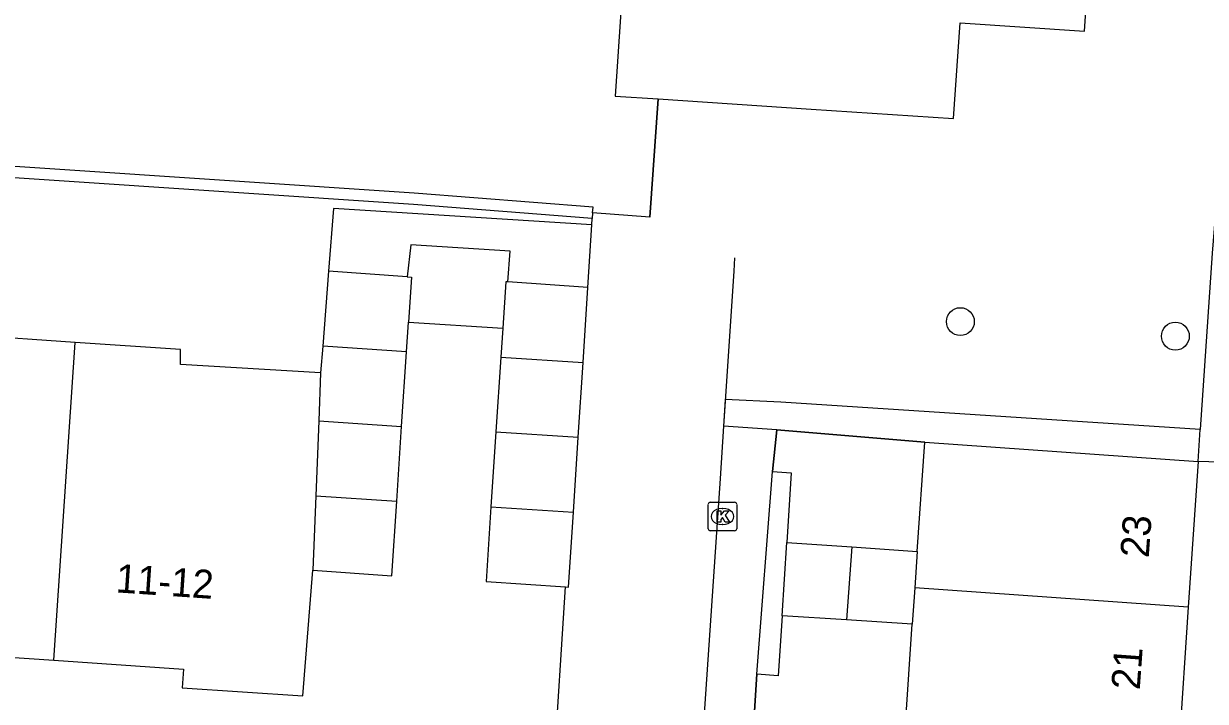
# Model space of a CAD drawing. Extents: x 161848 to 162726, y 385382 to 386521.
# Drawn here: x 162080.86 to 162122.26, y 386033.22 to 386056.94 of the extents above; entities that cross this region are included whole.
import ezdxf

# ---------------------------------------------------------------- set-up
doc = ezdxf.new("R2010")
doc.units = 0
for name, color, linetype in [('IMGEO_Boom', 7, 'Continuous'), ('IMGEO_Damwand', 7, 'Continuous'), ('IMGEO_Groenvoorziening', 7, 'Continuous'), ('IMGEO_Haag', 7, 'Continuous'), ('IMGEO_Hek', 7, 'Continuous'), ('IMGEO_Kolk', 7, 'Continuous'), ('IMGEO_Pand', 7, 'Continuous'), ('IMGEO_Pand_nummerreeks', 7, 'Continuous'), ('IMGEO_Voetpad_halfverhard', 7, 'Continuous'), ('IMGEO_Voetpad_open', 7, 'Continuous')]:
    doc.layers.add(name, color=color, linetype=linetype)

msp = doc.modelspace()

# ---------------------------------------------------------------- linework, layer by layer
at = {"layer": 'IMGEO_Boom'}
for centre in [(162113.677, 386046.507), (162121.21, 386045.999)]:
    msp.add_circle(centre, 0.489, dxfattribs=at)
at = {"layer": 'IMGEO_Damwand'}
for points in [[(162105.766, 386048.746), (162105.735, 386048.277), (162105.38, 386042.85), (162105.26, 386041.013)], [(162105.26, 386041.013), (162103.776, 386019.241), (162091.113, 386020.133), (162083.134, 386020.713), (162082.474, 386020.761)]]:
    msp.add_lwpolyline(points, dxfattribs=at)
at = {"layer": 'IMGEO_Groenvoorziening'}
for points in [[(162103.084, 386054.304), (162102.793, 386050.163), (162100.793, 386050.312)], [(162100.767, 386049.898), (162100.78, 386050.112)], [(162122.074, 386042.731), (162107.39, 386043.69), (162105.441, 386043.783), (162105.38, 386042.85)], [(162107.252, 386042.725), (162112.428, 386042.293)], [(162107.094, 386041.261), (162107.746, 386041.216), (162107.591, 386038.776)], [(162099.348, 386030.837), (162099.439, 386030.831), (162099.839, 386037.224)], [(162107.428, 386036.211), (162107.295, 386034.114), (162106.551, 386034.165)]]:
    msp.add_lwpolyline(points, dxfattribs=at)
at = {"layer": 'IMGEO_Haag'}
for points in [[(162100.793, 386050.312), (162100.809, 386050.511), (162094.545, 386051.001), (162049.411, 386054.017)], [(162100.78, 386050.112), (162094.517, 386050.603), (162049.384, 386053.618), (162049.397, 386053.818)], [(162100.793, 386050.312), (162100.78, 386050.112)]]:
    msp.add_lwpolyline(points, dxfattribs=at)
at = {"layer": 'IMGEO_Hek'}
for points in [[(162102.793, 386050.163), (162103.084, 386054.304)], [(162107.252, 386042.725), (162107.094, 386041.261)], [(162112.428, 386042.293), (162107.252, 386042.725)], [(162107.094, 386041.261), (162107.746, 386041.216), (162107.591, 386038.776)], [(162107.428, 386036.211), (162107.295, 386034.114), (162106.551, 386034.165)], [(162106.551, 386034.165), (162106.374, 386031.394)]]:
    msp.add_lwpolyline(points, dxfattribs=at)
at = {"layer": 'IMGEO_Kolk'}
for p, q in [((162104.84, 386039.26), (162104.84, 386040.112)), ((162104.915, 386040.186), (162105.767, 386040.186)), ((162105.328, 386039.966), (162105.353, 386039.966)), ((162105.841, 386040.112), (162105.841, 386039.26)), ((162105.767, 386039.186), (162104.915, 386039.186)), ((162105.351, 386039.406), (162105.326, 386039.406))]:
    msp.add_line(p, q, dxfattribs=at)
for points in [[(162104.84, 386039.26), (162104.84, 386040.112)], [(162104.915, 386040.186), (162105.767, 386040.186)], [(162105.161, 386039.886), (162105.284, 386039.886), (162105.284, 386039.735), (162105.414, 386039.886), (162105.578, 386039.886), (162105.432, 386039.735), (162105.585, 386039.486), (162105.433, 386039.486), (162105.348, 386039.65), (162105.284, 386039.583), (162105.284, 386039.486), (162105.161, 386039.486), (162105.161, 386039.886)], [(162105.841, 386040.112), (162105.841, 386039.26)], [(162105.767, 386039.186), (162104.915, 386039.186)]]:
    msp.add_lwpolyline(points, dxfattribs=at)
for centre, start, end in [((162104.917, 386040.11), 91.552, 178.448), ((162104.917, 386040.11), 91.552, 178.448), ((162105.765, 386040.11), 1.552, 88.448), ((162105.765, 386040.11), 1.552, 88.448), ((162104.917, 386039.262), 181.552, 268.448), ((162104.917, 386039.262), 181.552, 268.448), ((162105.765, 386039.262), 271.552, 358.448), ((162105.765, 386039.262), 271.552, 358.448)]:
    msp.add_arc(centre, 0.0765, start, end, dxfattribs=at)
for centre, major_axis, ratio, start_param, end_param in [((162105.327, 386039.686), (-0.387, 0.002), 0.722429, 4.712389, 7.853982), ((162105.352, 386039.686), (-0.39, 0.002), 0.717154, 1.570796, 4.712389)]:
    msp.add_ellipse(centre, major_axis=major_axis, ratio=ratio, start_param=start_param, end_param=end_param, dxfattribs=at)
at = {"layer": 'IMGEO_Pand'}
for points in [[(162103.084, 386054.304), (162108.452, 386053.946), (162113.44, 386053.614), (162113.664, 386056.962), (162118.028, 386056.671), (162118.642, 386065.873), (162114.274, 386066.165), (162114.973, 386076.64), (162109.771, 386076.987), (162110.19, 386083.26), (162108.794, 386083.353)], [(162091.103, 386077.734), (162090.775, 386072.799), (162090.435, 386067.702), (162102.421, 386066.903), (162101.588, 386054.404), (162103.084, 386054.304)], [(162100.767, 386049.898), (162091.712, 386050.469), (162091.541, 386048.276)], [(162100.625, 386047.703), (162100.767, 386049.898)], [(162097.825, 386047.896), (162097.901, 386048.97), (162094.42, 386049.194), (162094.289, 386048.078)], [(162091.541, 386048.276), (162091.336, 386045.647)], [(162094.289, 386048.078), (162091.541, 386048.276)], [(162094.289, 386048.078), (162094.445, 386048.067), (162094.341, 386046.487)], [(162097.825, 386047.896), (162097.756, 386047.901), (162097.648, 386046.283)], [(162100.625, 386047.703), (162097.825, 386047.896)], [(162100.456, 386045.082), (162100.625, 386047.703)], [(162094.273, 386045.454), (162094.341, 386046.487)], [(162094.341, 386046.487), (162097.648, 386046.283)], [(162097.648, 386046.283), (162097.58, 386045.267)], [(162082.667, 386045.779), (162078.977, 386046.029), (162078.95, 386045.517), (162074.049, 386045.837)], [(162081.914, 386034.653), (162082.667, 386045.779)], [(162091.263, 386044.717), (162086.349, 386045.003), (162086.358, 386045.529), (162082.667, 386045.779)], [(162091.336, 386045.647), (162091.263, 386044.717)], [(162094.273, 386045.454), (162091.336, 386045.647)], [(162094.101, 386042.841), (162094.273, 386045.454)], [(162097.58, 386045.267), (162097.406, 386042.646)], [(162097.58, 386045.267), (162100.456, 386045.082)], [(162100.287, 386042.46), (162100.456, 386045.082)], [(162091.263, 386044.717), (162091.195, 386043.032)], [(162091.195, 386043.032), (162091.089, 386040.414)], [(162091.195, 386043.032), (162094.101, 386042.841)], [(162093.93, 386040.228), (162094.101, 386042.841)], [(162097.406, 386042.646), (162097.231, 386040.025)], [(162097.406, 386042.646), (162100.287, 386042.46)], [(162100.117, 386039.839), (162100.287, 386042.46)], [(162112.165, 386038.462), (162112.428, 386042.293)], [(162112.428, 386042.293), (162122.011, 386041.611)], [(162122.011, 386041.611), (162121.664, 386036.509)], [(162091.089, 386040.414), (162090.984, 386037.804)], [(162091.089, 386040.414), (162093.93, 386040.228)], [(162090.984, 386037.804), (162093.758, 386037.615), (162093.93, 386040.228)], [(162097.231, 386040.025), (162097.057, 386037.41), (162099.839, 386037.224)], [(162097.231, 386040.025), (162100.117, 386039.839)], [(162099.839, 386037.224), (162099.948, 386037.217), (162100.117, 386039.839)], [(162107.428, 386036.211), (162107.591, 386038.776)], [(162107.591, 386038.776), (162109.878, 386038.619)], [(162109.878, 386038.619), (162109.691, 386036.067)], [(162109.878, 386038.619), (162112.165, 386038.462)], [(162112.165, 386038.462), (162112.078, 386037.191)], [(162081.914, 386034.653), (162086.459, 386034.346), (162086.415, 386033.692), (162090.642, 386033.414), (162090.984, 386037.804)], [(162112.078, 386037.191), (162111.991, 386035.921)], [(162121.664, 386036.509), (162112.078, 386037.191)], [(162121.664, 386036.509), (162121.339, 386031.726)], [(162109.691, 386036.067), (162107.428, 386036.211)], [(162111.991, 386035.921), (162109.691, 386036.067)], [(162111.75, 386032.408), (162111.991, 386035.921)], [(162073.288, 386034.59), (162077.368, 386034.304), (162077.41, 386034.958), (162081.914, 386034.653)]]:
    msp.add_lwpolyline(points, dxfattribs=at)
at = {"layer": 'IMGEO_Voetpad_halfverhard'}
for points in [[(162105.38, 386042.85), (162105.26, 386041.013), (162103.776, 386019.241), (162091.113, 386020.133), (162083.134, 386020.713)], [(162107.252, 386042.725), (162105.38, 386042.85)], [(162107.094, 386041.261), (162107.252, 386042.725)], [(162106.551, 386034.165), (162107.094, 386041.261)], [(162106.374, 386031.394), (162106.551, 386034.165)]]:
    msp.add_lwpolyline(points, dxfattribs=at)
at = {"layer": 'IMGEO_Voetpad_open'}
for points in [[(162125.487, 386090.674), (162122.884, 386053.657), (162122.5, 386048.906), (162122.074, 386042.731)], [(162122.011, 386041.611), (162122.074, 386042.731)], [(162123.495, 386041.562), (162122.011, 386041.611)]]:
    msp.add_lwpolyline(points, dxfattribs=at)

# ---------------------------------------------------------------- texts
at = {"layer": 'IMGEO_Pand_nummerreeks'}
for s, rotation, p in [('23', 85.9093, (162120.274, 386038.219)), ('23', 85.9093, (162120.274, 386038.219)), ('23', 85.9093, (162120.274, 386038.219)), ('23', 85.9093, (162120.274, 386038.219)), ('23', 85.9093, (162120.274, 386038.219)), ('23', 85.9093, (162120.274, 386038.219)), ('23', 85.9093, (162120.274, 386038.219)), ('23', 85.9093, (162120.274, 386038.219)), ('23', 85.9093, (162120.274, 386038.219)), ('11-12', 356.1268, (162084.066, 386037.033)), ('21', 85.915, (162119.96, 386033.598))]:
    msp.add_text(s, height=1, rotation=rotation, dxfattribs=at).set_placement(p)

doc.saveas('drawing.dxf')
